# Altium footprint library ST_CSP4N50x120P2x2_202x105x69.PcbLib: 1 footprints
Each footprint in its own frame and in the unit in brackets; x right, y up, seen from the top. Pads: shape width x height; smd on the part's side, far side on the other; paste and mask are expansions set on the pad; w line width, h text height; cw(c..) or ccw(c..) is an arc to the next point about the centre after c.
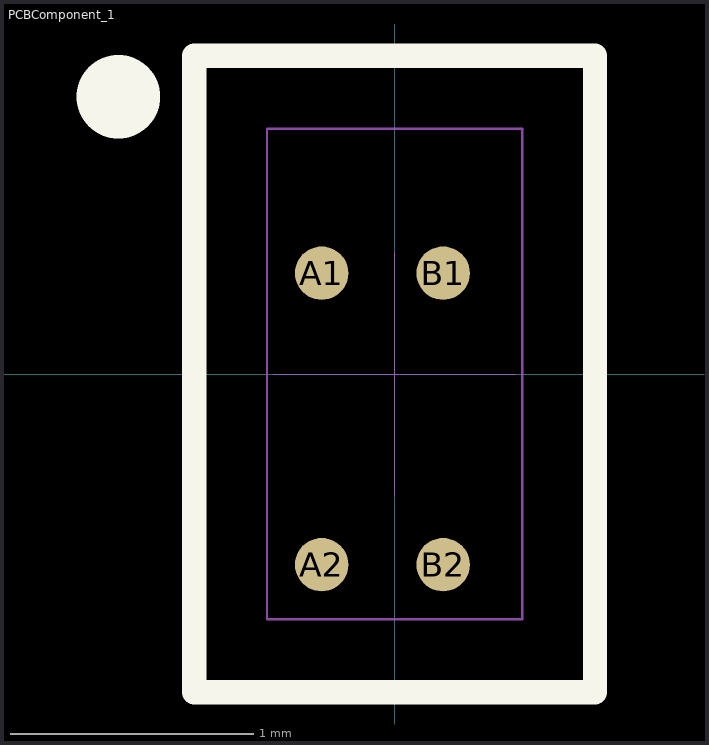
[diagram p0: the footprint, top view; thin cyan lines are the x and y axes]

## PCBComponent_1 [mm]
pads (4):
  round 0.22 smd paste-20 mask+0.05: A1(-0.3,0.415) A2(-0.3,-0.785) B1(0.2,0.415) B2(0.2,-0.785)
Top Overlay:
  circle w0.3: c-1.137,1.141 r0.022
  lines w0.1: -0.825,-1.31 -0.825,1.31 0.825,1.31 0.825,-1.31 -0.825,-1.31
Top Paste:
  rectangle: 0.09,-0.895 0.31,-0.675
  rectangle: -0.41,-0.895 -0.19,-0.675
  rectangle: 0.09,0.305 0.31,0.525
  rectangle: -0.41,0.305 -0.19,0.525
Mechanical 15:
  lines w0.001: -0.5,0 0.5,0 ; 0,-0.5 0,0.5
  lines w0.01: -0.525,-1.01 -0.525,1.01 0.525,1.01 0.525,-1.01 -0.525,-1.01
3D body: height 0.69, standoff 0.16, extent -0.525,-1.01 0.525,1.01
